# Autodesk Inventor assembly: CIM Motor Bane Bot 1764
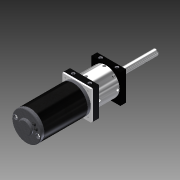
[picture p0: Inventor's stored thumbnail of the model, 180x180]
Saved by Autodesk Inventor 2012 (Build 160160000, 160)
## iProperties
Created: 2008-01
Part Number: CIM Motor Bane Bot 1764
Document SubType Name: Assembly
Designer: clee1
Author: clee1
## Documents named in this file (8)
- R:\CAD Archives\Motors_1764\CIM_Motor_Bane_Bots_1764\CIM_Motor_Bane_Bot_1764.iam
- R:\CAD Archives\Motors_1764\CIM_Motor_Bane_Bots_1764\BB2-Interface_Plate_1764.ipt
- R:\CAD Archives\Motors_1764\CIM_Motor_Bane_Bots_1764\BB2-Back_Plate_1764.ipt
- R:\CAD Archives\Motors_1764\CIM_Motor_Bane_Bots_1764\BB2-Front_Plate_1764.ipt
- R:\CAD Archives\Motors_1764\CIM_Motor_Bane_Bots_1764\CIM_Bearing_1764.ipt
- R:\CAD Archives\Motors_1764\CIM_Motor_Bane_Bots_1764\BB2-Ring_Gear_1764.ipt
- R:\CAD Archives\Motors_1764\CIM_Motor_Bane_Bots_1764\BB2-Output_Shaft_2008_Cut_1764.ipt
- R:\CAD Archives\Motors_1764\CIM_Motor_Bane_Bots_1764\CIM_Motor_1764.ipt
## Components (8 placed, 7 different names)
1. BB2-Interface_Plate_1764:1 — Mate:1, Flush:1, Flush:2, Mate:12
2. BB2-Back_Plate_1764:1 — Mate:1, Flush:1, Flush:2, Mate:5, Mate:6, Angle:1, Angle:2, Mate:11, Angle:4, Flush:3, Flush:4
3. BB2-Front_Plate_1764:1 — Angle:2, Tangent:1, Tangent:2, Mate:13, Flush:3, Flush:4, Flush:5
4. CIM_Bearing_1764:3 — Mate:3, Tangent:2
5. CIM_Bearing_1764:4 — Mate:3, Tangent:1, Tangent:3, Flush:5, Mate:14
6. BB2-Ring_Gear_1764:1 — Mate:5, Mate:6, Angle:1, Mate:13
7. BB2-Output_Shaft_2008_Cut_1764:1 — Tangent:3, Mate:14, Mate:15
8. CIM_Motor_1764:1 — Mate:11, Angle:4, Mate:12, Mate:15
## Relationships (20: Mate 9, Flush 5, Angle 3, Tangent 3)
- Mate:1: BB2-Interface_Plate_1764:1 ↔ BB2-Back_Plate_1764:1
- Flush:1: BB2-Interface_Plate_1764:1 ↔ BB2-Back_Plate_1764:1
- Flush:2: BB2-Interface_Plate_1764:1 ↔ BB2-Back_Plate_1764:1
- Mate:3: CIM_Bearing_1764:3 ↔ CIM_Bearing_1764:4
- Mate:5: BB2-Back_Plate_1764:1 ↔ BB2-Ring_Gear_1764:1
- Mate:6: BB2-Back_Plate_1764:1 ↔ BB2-Ring_Gear_1764:1
- Angle:1: BB2-Back_Plate_1764:1 ↔ BB2-Ring_Gear_1764:1
- Angle:2: BB2-Back_Plate_1764:1 ↔ BB2-Front_Plate_1764:1
- Mate:11: BB2-Back_Plate_1764:1 ↔ CIM_Motor_1764:1
- Angle:4: BB2-Back_Plate_1764:1 ↔ CIM_Motor_1764:1
- Mate:12: BB2-Interface_Plate_1764:1 ↔ CIM_Motor_1764:1
- Tangent:1: BB2-Front_Plate_1764:1 ↔ CIM_Bearing_1764:4
- Tangent:2: BB2-Front_Plate_1764:1 ↔ CIM_Bearing_1764:3
- Mate:13: BB2-Front_Plate_1764:1 ↔ BB2-Ring_Gear_1764:1
- Flush:3: BB2-Back_Plate_1764:1 ↔ BB2-Front_Plate_1764:1
- Tangent:3: CIM_Bearing_1764:4 ↔ BB2-Output_Shaft_2008_Cut_1764:1
- Flush:4: BB2-Back_Plate_1764:1 ↔ BB2-Front_Plate_1764:1
- Flush:5: BB2-Front_Plate_1764:1 ↔ CIM_Bearing_1764:4
- Mate:14: CIM_Bearing_1764:4 ↔ BB2-Output_Shaft_2008_Cut_1764:1
- Mate:15: BB2-Output_Shaft_2008_Cut_1764:1 ↔ CIM_Motor_1764:1
